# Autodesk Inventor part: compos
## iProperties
Author: chr
Created: 2001-06
Part Number: compos
Material: Par défaut
Document SubType Name: Modélisation
Designer: chr
Control State: 0
Master: False
Checked Out: False
PropertySet Name: Design Tracking Control
Shininess: 20.0
PropertySet Name: _Private Model Information
Length Units: 11269
Angle Units: 11286
Time Units: 11279
Mass Units: 11290
Length Display Precision: 3
Angle Display Precision: 2
Compacted: False
Density: 0.0
Volumn: 0.0
Area: 0.0
PropertySet Name: Model Information
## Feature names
1. Extrusion1
2. Extrusion2
